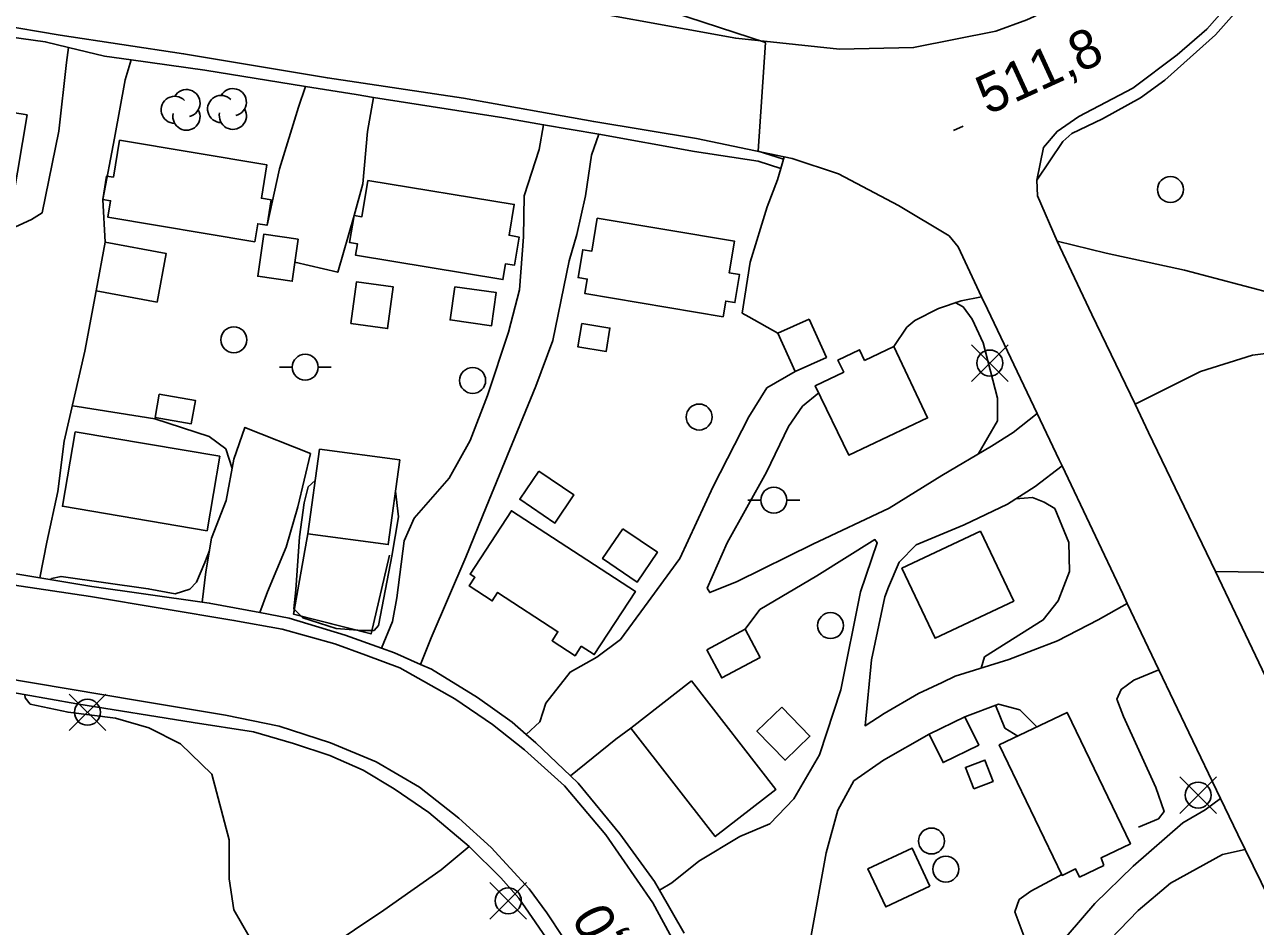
# Model space of a CAD drawing. Extents: x 347059 to 352153, y 6073752 to 6078601.
# Drawn here: x 348771.1 to 348913.3, y 6074780.5 to 6074884.7 of the extents above; entities that cross this region are included whole.
import ezdxf

# ---------------------------------------------------------------- set-up
doc = ezdxf.new("R2010")
doc.units = 0
for name, color, linetype in [('Level 19', 7, 'Continuous'), ('Level 2', 7, 'Continuous'), ('Level 21', 7, 'Continuous'), ('Level 22', 7, 'Continuous'), ('Level 3', 7, 'Continuous'), ('Level 31', 7, 'Continuous'), ('Level 36', 7, 'Continuous'), ('Level 37', 7, 'Continuous'), ('Level 44', 7, 'Continuous')]:
    doc.layers.add(name, color=color, linetype=linetype)

msp = doc.modelspace()

# ---------------------------------------------------------------- linework, layer by layer
at = {"layer": 'Level 19'}
for points in [[(348761.84, 6074884.32), (348761.55, 6074882.91), (348759.87, 6074877.76), (348756.99, 6074865.76), (348754.2, 6074859.34), (348752.62, 6074852.65), (348753.7, 6074850.95), (348755.61, 6074849.35), (348758.55, 6074850.15), (348762.19, 6074853.21), (348764.04, 6074856.44), (348766.05, 6074858.74), (348769.11, 6074860.86), (348771.93, 6074862.16), (348773.16, 6074862.94), (348775.11, 6074872.38), (348775.97, 6074880.32), (348776.22, 6074882.07)], [(348783.47, 6074880.64), (348782.77, 6074878.32), (348781.52, 6074871.57), (348780.17, 6074864.5), (348780.45, 6074859.55)], [(348799.16, 6074861.51), (348800.59, 6074868.04), (348802.81, 6074875.15), (348803.59, 6074877.56)], [(348811.47, 6074876.29), (348810.78, 6074872.34), (348810.22, 6074866.3), (348809.22, 6074862.65), (348807.32, 6074856.08), (348802.38, 6074857.24)], [(348812.37, 6074812.64), (348813.65, 6074815.69), (348814.15, 6074818.44), (348815.02, 6074825.02), (348816.14, 6074827.65), (348820.2, 6074832.29), (348822.64, 6074836.64), (348824.64, 6074841.84), (348827.06, 6074849.16), (348828.33, 6074854.05), (348828.8, 6074860.18), (348828.86, 6074864.89), (348830.58, 6074870.25), (348831.11, 6074873.13)], [(348816.9, 6074810.75), (348818.13, 6074813.8), (348822.13, 6074823.13), (348824.47, 6074828.93), (348830.23, 6074842.91), (348832.17, 6074848.2), (348834.06, 6074857.41), (348834.94, 6074860.43), (348835.96, 6074864.91), (348836.64, 6074869.61), (348837.49, 6074872.03)], [(348858.92, 6074869.41), (348858.51, 6074868.07), (348858.12, 6074866.77), (348856.95, 6074863.64), (348854.97, 6074857.24), (348854.07, 6074851.35), (348854.82, 6074850.92), (348858.18, 6074849.04)], [(348772.9, 6074820.74), (348773.7, 6074824.86), (348774.98, 6074830.75), (348775.73, 6074836.56), (348778.12, 6074846.96), (348779.42, 6074853.92)], [(348881.72, 6074853.25), (348879.35, 6074852.79), (348876.72, 6074851.87), (348874, 6074850.49), (348873.07, 6074849.71), (348871.59, 6074847.49)], [(348829.1, 6074802.65), (348830.67, 6074804.1), (348831.37, 6074806.26), (348834.17, 6074809.86), (348837.28, 6074811.57), (348840, 6074813.64), (348842.75, 6074817.41), (348846.84, 6074823), (348850.7, 6074831.3), (348854.84, 6074839.37), (348856.89, 6074842.71), (348860.16, 6074844.61)], [(348888.14, 6074839.76), (348885.38, 6074837.56), (348882.86, 6074835.96), (348877.13, 6074832.58), (348871.04, 6074828.82), (348862.2, 6074824.64), (348853.47, 6074820.33), (348850.31, 6074819.04), (348850.02, 6074819.56), (348852.31, 6074824.78), (348856.87, 6074832.97), (348859.41, 6074838.25), (348861.01, 6074840.59), (348862.9, 6074842.13)], [(348791.66, 6074817.95), (348792.07, 6074821.45), (348792.76, 6074825.34), (348794.44, 6074829.71), (348795.32, 6074834.45), (348796.61, 6074838.14), (348804.17, 6074835.12)], [(348798.33, 6074816.74), (348799.23, 6074819.13), (348801.35, 6074824.28), (348802.73, 6074828.96), (348804.17, 6074835.12)], [(348898.55, 6074817.77), (348895.19, 6074815.89), (348890.49, 6074813.45), (348884.86, 6074811.3), (348878.68, 6074809.37), (348877.14, 6074808.66), (348874.43, 6074807.37), (348870.45, 6074805.07), (348868.26, 6074803.66), (348868.98, 6074811.29), (348870.53, 6074818.55), (348870.95, 6074819.68), (348872.2, 6074822.58), (348874.17, 6074824.56), (348879.7, 6074826.89), (348884.69, 6074829.26), (348887.91, 6074831.29), (348891.03, 6074833.69)], [(348844.49, 6074784.66), (348845.91, 6074785.51), (348849.04, 6074788), (348853.77, 6074790.85), (348857.23, 6074792.32), (348860.01, 6074795.2), (348862.99, 6074800.31), (348865.47, 6074807.82), (348867.73, 6074819.12), (348869.65, 6074824.78), (348869.39, 6074825.17), (348862.69, 6074820.97), (348856.1, 6074817.09), (348854.39, 6074814.8)], [(348902.21, 6074810.13), (348899.29, 6074808.93), (348897.84, 6074807.86), (348897.34, 6074806.74), (348898.12, 6074804.73), (348901.84, 6074796.5), (348902.8, 6074793.73), (348902.15, 6074792.88), (348899.85, 6074791.93)], [(348879.77, 6074804.7), (348883.67, 6074806.15), (348886.15, 6074805.5), (348888.1, 6074803.52)], [(348834.23, 6074797.87), (348839.45, 6074802.11), (348841.18, 6074803.36)], [(348909.32, 6074795.26), (348907.56, 6074793.93), (348904.96, 6074792.43), (348899.21, 6074787.43), (348894.81, 6074783.11), (348890.05, 6074777.59), (348885.84, 6074772.68), (348882.81, 6074769.98), (348879.8, 6074767.45), (348875.65, 6074765.02), (348872.29, 6074763.26), (348867.66, 6074761.8), (348866.35, 6074761.92), (348864.14, 6074762.79), (348862.75, 6074764.67), (348861.5, 6074768.18), (348861.68, 6074772.89), (348862.01, 6074779.41), (348863.76, 6074788.95), (348865.11, 6074793.88), (348866.97, 6074797.27), (348870.38, 6074799.69), (348875.65, 6074802.67)], [(348883.57, 6074760.87), (348882.4, 6074764.15), (348882.48, 6074765.08), (348885.63, 6074768.35), (348890.9, 6074772.72), (348895.49, 6074777.81), (348899.82, 6074782.31), (348903.55, 6074785.45), (348909.56, 6074788.76), (348912.17, 6074789.36)]]:
    msp.add_lwpolyline(points, dxfattribs=at)
at = {"layer": 'Level 2'}
for points in [[(348858.84, 6074869.13), (348855.89, 6074870.08), (348856.73, 6074882.65), (348846, 6074886.14), (348830.12, 6074889.51), (348810.63, 6074895.11), (348793.24, 6074900.19), (348783.68, 6074903.16), (348773.22, 6074905.13), (348758.94, 6074906.04), (348748.37, 6074906.85)], [(348881.3, 6074835.04), (348883.55, 6074838.91), (348883.56, 6074841.52), (348881.91, 6074847.92), (348880.61, 6074850.65), (348879.57, 6074852.06), (348878.68, 6074852.56)], [(348795.12, 6074833.4), (348794.4, 6074835.66), (348792.47, 6074837.1), (348786.21, 6074839.13), (348777.22, 6074840.55), (348776.66, 6074840.63)], [(348814.01, 6074830.78), (348814.36, 6074827.8), (348813.59, 6074823.27), (348812.46, 6074817.44), (348812.02, 6074815.25), (348811.52, 6074814.67), (348810.16, 6074814.68), (348807.15, 6074814.88), (348803.28, 6074816.12), (348802.26, 6074817.17), (348802.5, 6074819.35), (348802.92, 6074825.49), (348803.43, 6074829.42), (348803.92, 6074831.28), (348804.71, 6074831.99)], [(348881.67, 6074810.3), (348882.05, 6074811.61), (348888.84, 6074815.89), (348890.55, 6074818.1), (348891.87, 6074821.5), (348891.78, 6074824.85), (348890.16, 6074828.76), (348888.95, 6074829.49), (348887.59, 6074830.03), (348885.66, 6074829.87)], [(348774.16, 6074820.54), (348774.26, 6074820.68), (348775.36, 6074820.91), (348785.44, 6074819.49), (348788.53, 6074818.91), (348790.24, 6074819.44), (348791.02, 6074820.26), (348791.99, 6074822.51), (348792.51, 6074823.93)], [(348781.65, 6074804.54), (348776.17, 6074805.21), (348771.8, 6074806.16), (348771.2, 6074806.89), (348771.19, 6074807.23)], [(348885.89, 6074802.45), (348884.41, 6074803.38), (348883.33, 6074806.03)], [(348797.08, 6074779.28), (348795.33, 6074782.37), (348794.77, 6074785.96), (348794.79, 6074790.45), (348792.77, 6074798.05), (348789.15, 6074801.56), (348785.5, 6074803.4), (348781.65, 6074804.54)], [(348888.71, 6074776.03), (348886.61, 6074779.37), (348885.57, 6074782.15), (348886.05, 6074783.55), (348887.42, 6074784.55), (348890.65, 6074786.28), (348890.96, 6074786.47)]]:
    msp.add_lwpolyline(points, dxfattribs=at)
at = {"layer": 'Level 21'}
for points in [[(348764.32, 6074897.6), (348787.23, 6074894.27), (348810.07, 6074890.73), (348829.95, 6074887.38), (348853.31, 6074883.13), (348865.3, 6074881.86), (348873.86, 6074882.04), (348883.35, 6074883.93), (348886.93, 6074885.27), (348892.68, 6074887.91), (348896.25, 6074890.53), (348900.3, 6074894.03), (348903.11, 6074898.01), (348905.99, 6074903.35), (348909.08, 6074912.08)], [(348914.53, 6074809.33), (348908.74, 6074821.47), (348901.01, 6074837.56), (348899.44, 6074840.82), (348894.44, 6074851.19), (348890.44, 6074859.66), (348888.16, 6074864.92), (348888.1, 6074866.71), (348888.87, 6074870.5), (348890.43, 6074872.35), (348892.93, 6074874.07), (348899.19, 6074877.37), (348904.3, 6074881.22), (348907.73, 6074884.19), (348911.92, 6074888.95), (348915.78, 6074894.66)], [(348760.68, 6074885.95), (348775.27, 6074883.49), (348789.51, 6074881.34), (348806.14, 6074878.53), (348821.84, 6074876.18), (348836.9, 6074873.5), (348848.79, 6074871.53), (348858.92, 6074869.41), (348859.83, 6074869.22), (348865.18, 6074867.46), (348872.1, 6074863.81), (348877.95, 6074860.27), (348879, 6074859.01), (348881.72, 6074853.25), (348882.41, 6074851.79), (348888.14, 6074839.76), (348890.69, 6074834.4), (348891.03, 6074833.69), (348898.02, 6074818.89), (348898.55, 6074817.77), (348902.21, 6074810.13), (348905.67, 6074802.89), (348909.32, 6074795.26), (348911.32, 6074791.1), (348912.17, 6074789.36), (348916.77, 6074779.9)], [(348847.42, 6074776.38), (348843.75, 6074783.19), (348838.3, 6074791.03), (348833.54, 6074796.7), (348828.89, 6074800.87), (348825.22, 6074803.8), (348820.85, 6074806.75), (348814.51, 6074810.33), (348810.59, 6074811.83), (348806.99, 6074813.14), (348800.9, 6074814.8), (348795.34, 6074815.83), (348778.78, 6074818.59), (348761.95, 6074821.11)], [(348833.36, 6074779.17), (348831.49, 6074782.02), (348829.46, 6074784.81), (348825.07, 6074789.57), (348821.31, 6074792.96), (348816.78, 6074796.55), (348811.75, 6074799.47), (348806.49, 6074801.68), (348800.55, 6074803.61), (348794.34, 6074804.86), (348784.18, 6074806.59), (348768.4, 6074809.23)]]:
    msp.add_lwpolyline(points, dxfattribs=at)
at = {"layer": 'Level 22'}
for points in [[(348888.1, 6074866.71), (348891.11, 6074871.18), (348892.14, 6074872.12), (348895.67, 6074873.8), (348900.08, 6074876.22), (348902.89, 6074878.29), (348908.74, 6074883.53), (348912.75, 6074888.06), (348916.05, 6074892.53), (348917.29, 6074894.8), (348918.45, 6074896.92), (348920.12, 6074900.63), (348922.33, 6074907.77), (348923.41, 6074913.28), (348924.2, 6074919.22), (348924.19, 6074925.57), (348923.58, 6074929.57), (348922.12, 6074935.85), (348918.49, 6074946.72), (348916.92, 6074946.17)], [(348734.86, 6074888.16), (348735.7, 6074888), (348737.98, 6074887.79), (348750.17, 6074886.5), (348758.09, 6074884.84), (348761.84, 6074884.32), (348773.53, 6074882.72), (348776.22, 6074882.07), (348780.38, 6074881.07), (348783.47, 6074880.64), (348791.97, 6074879.45), (348803.59, 6074877.56), (348809.46, 6074876.61), (348811.47, 6074876.29), (348826.5, 6074873.92), (348831.11, 6074873.13), (348837.49, 6074872.03), (348848.56, 6074870.05), (348855.89, 6074868.9), (348858.51, 6074868.07)], [(348890.44, 6074859.66), (348896.09, 6074858.3), (348905.17, 6074856.33), (348922.68, 6074851.7), (348939, 6074848.51), (348952.63, 6074847.79), (348965.05, 6074846.51), (348982.63, 6074844.7), (348994.37, 6074843.16), (349003.61, 6074843.32), (349008.7, 6074844.01), (349021.04, 6074845.66), (349029.27, 6074848.49)], [(348899.44, 6074840.82), (348907.02, 6074844.62), (348913.03, 6074846.48), (348922.62, 6074847.7), (348939, 6074848.51)], [(348908.74, 6074821.47), (348921.92, 6074821.29), (348929.97, 6074821.82), (348938.38, 6074822.81), (348949.89, 6074823.36), (348961.54, 6074825.55), (348970.82, 6074826.05), (348976.55, 6074824.63), (348986.72, 6074822.06), (348996.49, 6074821.61), (349003.63, 6074824.12), (349008.14, 6074826.86), (349011.57, 6074830.36), (349015.81, 6074837.41), (349017.53, 6074840.26), (349021.04, 6074845.66)], [(348847.35, 6074779.67), (348844.49, 6074784.66), (348843.94, 6074785.63), (348839.9, 6074791.15), (348835.12, 6074797.03), (348834.23, 6074797.87), (348830.23, 6074801.67), (348829.1, 6074802.65), (348827.46, 6074804.07), (348823.49, 6074806.9), (348818.16, 6074810.18), (348816.9, 6074810.75), (348813.9, 6074812.09), (348812.37, 6074812.64), (348808.18, 6074814.13), (348801.7, 6074816.07), (348798.33, 6074816.74), (348792.48, 6074817.84), (348791.66, 6074817.95), (348778.91, 6074819.75), (348772.9, 6074820.74), (348765.44, 6074821.98)], [(348764.98, 6074808.33), (348777.17, 6074806.17), (348790.64, 6074804.02), (348797.6, 6074802.95), (348802.23, 6074801.59), (348806.4, 6074800.23), (348810.26, 6074798.52), (348813.83, 6074796.35), (348817.85, 6074793.64), (348822.51, 6074789.71), (348826.17, 6074786.08), (348828.24, 6074783.71), (348832.54, 6074777.5)], [(348822.51, 6074789.71), (348819.26, 6074787.01), (348812.65, 6074782.35), (348802.35, 6074775.42), (348788.81, 6074766.15), (348779.08, 6074759.41), (348770.7, 6074753.66), (348747.81, 6074739.05), (348741.77, 6074736.18), (348736.56, 6074734.23), (348733.32, 6074732.88), (348727.07, 6074730.28), (348720.41, 6074728.26), (348713.32, 6074725.86), (348706.38, 6074723.37), (348700.42, 6074721.78), (348696.49, 6074721.36), (348692.52, 6074722.36)]]:
    msp.add_lwpolyline(points, dxfattribs=at)
at = {"layer": 'Level 3'}
msp.add_line((348878.48, 6074872.47), (348879.57, 6074872.97), dxfattribs=at)
at = {"layer": 'Level 31'}
for points in [[(348762.21, 6074875.79), (348771.43, 6074874.26), (348769.8, 6074864.44), (348760.58, 6074865.97), (348762.21, 6074875.79)], [(348782.12, 6074871.33), (348799.14, 6074868.49), (348798.5, 6074864.63), (348799.65, 6074864.44), (348799.16, 6074861.51), (348798.09, 6074861.69), (348797.74, 6074859.6), (348780.77, 6074862.43), (348781.09, 6074864.35), (348780.17, 6074864.5), (348780.62, 6074867.2), (348781.41, 6074867.07), (348782.12, 6074871.33)], [(348810.81, 6074866.69), (348827.71, 6074863.91), (348827.12, 6074860.35), (348828.28, 6074860.15), (348827.74, 6074856.88), (348826.71, 6074857.05), (348826.41, 6074855.23), (348809.39, 6074858.04), (348809.61, 6074859.35), (348808.7, 6074859.5), (348809.22, 6074862.65), (348810.12, 6074862.5), (348810.81, 6074866.69)], [(348837.3, 6074862.31), (348853.17, 6074859.65), (348852.56, 6074856), (348853.76, 6074855.8), (348853.22, 6074852.56), (348852.15, 6074852.74), (348851.85, 6074850.94), (348835.88, 6074853.61), (348836.16, 6074855.28), (348835.1, 6074855.46), (348835.63, 6074858.67), (348836.67, 6074858.5), (348837.3, 6074862.31)], [(348786.48, 6074852.63), (348779.42, 6074853.92), (348780.45, 6074859.55), (348787.5, 6074858.26), (348786.48, 6074852.63)], [(348802.76, 6074859.9), (348802.07, 6074855.04), (348798.09, 6074855.61), (348798.78, 6074860.46), (348802.76, 6074859.9)], [(348808.84, 6074850.14), (348809.48, 6074854.96), (348813.73, 6074854.39), (348813.08, 6074849.57), (348808.84, 6074850.14)], [(348820.84, 6074854.4), (348825.64, 6074853.72), (348825.1, 6074849.89), (348820.3, 6074850.56), (348820.84, 6074854.4)], [(348835.52, 6074850.16), (348838.77, 6074849.62), (348838.32, 6074846.9), (348835.07, 6074847.44), (348835.52, 6074850.16)], [(348861.81, 6074850.66), (348863.79, 6074846.23), (348860.16, 6074844.61), (348858.18, 6074849.04), (348861.81, 6074850.66)], [(348868.2, 6074845.89), (348871.59, 6074847.49), (348875.48, 6074839.24), (348866.36, 6074834.94), (348862.5, 6074842.95), (348865.78, 6074844.53), (348865.12, 6074845.92), (348867.61, 6074847.11), (348868.2, 6074845.89)], [(348786.71, 6074842), (348790.89, 6074841.26), (348790.41, 6074838.56), (348786.23, 6074839.3), (348786.71, 6074842)], [(348776.98, 6074837.62), (348793.69, 6074834.8), (348792.23, 6074826.19), (348775.52, 6074829.02), (348776.98, 6074837.62)], [(348805.2, 6074835.63), (348814.5, 6074834.38), (348813.17, 6074824.59), (348803.88, 6074825.85), (348805.2, 6074835.63)], [(348830.57, 6074833.1), (348834.62, 6074830.34), (348832.41, 6074827.09), (348828.36, 6074829.84), (348830.57, 6074833.1)], [(348835.46, 6074812.85), (348834.74, 6074811.74), (348832.09, 6074813.47), (348832.77, 6074814.52), (348825.8, 6074819.06), (348825.17, 6074818.09), (348822.52, 6074819.81), (348823.17, 6074820.81), (348822.62, 6074821.17), (348827.39, 6074828.5), (348841.72, 6074819.18), (348836.96, 6074811.87), (348835.46, 6074812.85)], [(348840.26, 6074826.42), (348844.27, 6074823.71), (348841.94, 6074820.26), (348837.93, 6074822.97), (348840.26, 6074826.42)], [(348881.57, 6074826.16), (348885.42, 6074818.07), (348876.35, 6074813.76), (348872.51, 6074821.85), (348881.57, 6074826.16)], [(348849.96, 6074812.43), (348854.39, 6074814.8), (348856.13, 6074811.55), (348851.7, 6074809.18), (348849.96, 6074812.43)], [(348848.2, 6074808.83), (348857.96, 6074796.3), (348850.94, 6074790.84), (348841.18, 6074803.36), (348848.2, 6074808.83)], [(348858.62, 6074805.81), (348861.88, 6074802.46), (348859.01, 6074799.67), (348855.76, 6074803.01), (348858.62, 6074805.81)], [(348875.65, 6074802.67), (348879.77, 6074804.7), (348881.38, 6074801.42), (348877.26, 6074799.39), (348875.65, 6074802.67)], [(348895.84, 6074787.51), (348893.03, 6074786.15), (348892.58, 6074787.1), (348891.02, 6074786.35), (348883.76, 6074801.43), (348891.6, 6074805.2), (348898.9, 6074790.02), (348895.52, 6074788.39), (348895.84, 6074787.51)], [(348880.8, 6074796.36), (348879.85, 6074798.83), (348882.09, 6074799.69), (348883.04, 6074797.21), (348880.8, 6074796.36)], [(348875.75, 6074785.11), (348870.66, 6074782.72), (348868.59, 6074787.13), (348873.68, 6074789.52), (348875.75, 6074785.11)]]:
    msp.add_lwpolyline(points, dxfattribs=at)
at = {"layer": 'Level 36'}
for p, q in [((348884.77, 6074843.46), (348880.54, 6074847.69)), ((348880.54, 6074843.46), (348884.77, 6074847.69)), ((348800.58, 6074845.1), (348802.08, 6074845.1)), ((348806.58, 6074845.1), (348805.08, 6074845.1)), ((348854.72, 6074829.73), (348856.22, 6074829.73)), ((348860.72, 6074829.73), (348859.22, 6074829.73)), ((348780.52, 6074803.09), (348776.29, 6074807.32)), ((348776.29, 6074803.09), (348780.52, 6074807.32)), ((348908.84, 6074793.52), (348904.61, 6074797.75)), ((348904.61, 6074793.52), (348908.84, 6074797.75)), ((348829.14, 6074781.3), (348824.91, 6074785.53)), ((348824.91, 6074781.3), (348829.14, 6074785.53))]:
    msp.add_line(p, q, dxfattribs=at)
for centre in [(348903.53, 6074865.64), (348795.32, 6074848.27), (348882.66, 6074845.58), (348803.57, 6074845.1), (348822.91, 6074843.57), (348849.08, 6074839.34), (348857.71, 6074829.73), (348864.26, 6074815.23), (348778.41, 6074805.21), (348906.73, 6074795.64), (348875.92, 6074790.33), (348877.58, 6074787.08), (348827.03, 6074783.42)]:
    msp.add_circle(centre, 1.5, dxfattribs=at)
at = {"layer": 'Level 37'}
for points in [[(348813.29, 6074823.36), (348811.18, 6074814.26), (348802.23, 6074816.54), (348803.91, 6074826.06)], [(348807.52, 6074815.19), (348802.23, 6074816.54), (348802.32, 6074817.07)]]:
    msp.add_lwpolyline(points, dxfattribs=at)
at = {"layer": 'Level 44'}
for centre, start, end in [((348789.85, 6074875.63), 282.2692, 149.7263), ((348795.21, 6074875.73), 282.2692, 149.7263), ((348788.5, 6074874.85), 44.1154, 269.804), ((348793.86, 6074874.95), 44.1154, 269.804), ((348789.85, 6074874.06), 166.9369, 29.6212), ((348795.21, 6074874.16), 166.9369, 29.6212)]:
    msp.add_arc(centre, 1.57, start, end, dxfattribs=at)

# ---------------------------------------------------------------- texts
at = {"layer": 'Level 3'}
for s, rotation, p in [('511,8', 24.642, (348882.43, 6074874.22)), ('513,0', 117.676, (348845.25, 6074770.24))]:
    msp.add_text(s, height=4.5, rotation=rotation, dxfattribs=at).set_placement(p)

doc.saveas('drawing.dxf')
